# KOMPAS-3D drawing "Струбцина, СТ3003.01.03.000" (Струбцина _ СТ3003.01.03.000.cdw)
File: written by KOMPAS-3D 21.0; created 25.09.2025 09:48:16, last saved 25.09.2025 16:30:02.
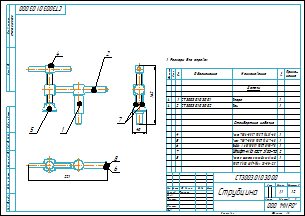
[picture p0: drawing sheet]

Sheet 1: A3, landscape

Document properties: Масса: 1.103282

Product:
- Part/product: Струбцина  | designation СТ3003.01.03.000
    Масса: 1.103282
    Форматы листов документа: A3
  - Component [detail]: Опора  | designation СТ3003.01.03.001  | pos. 1  | Материал: Круг$d30 ГОСТ 2590-2006;40Х ГОСТ 4543-2016$ (density 7850 kg/m3); Масса: 0.339602; Форматы листов документа: A4; source file: ..\..\3D\Струбцина _ СТ3003.01.03.000\Опора _ СТ3003.01.03.001.m3d, Опора _ СТ3003.01.03.001.cdw
  - Component [detail]: Ось  | designation СТ3003.01.03.002  | pos. 2  | Материал: Круг$d30 ГОСТ 2590-2006;40Х ГОСТ 4543-2016$ (density 7850 kg/m3); Масса: 0.346686; Форматы листов документа: A4; source file: ..\..\3D\Струбцина _ СТ3003.01.03.000\Ось _ СТ3003.01.03.002.m3d, Ось _ СТ3003.01.03.002.cdw
  - Component [standard]: Штифт 4x16 ГОСТ 3128-70  | qty 2  | pos. 7  | Материал: Сталь 45 ГОСТ 1050-88 (density 1000 kg/m3); Масса: 0.00158; Раздел спецификации: Стандартные изделия; Рассекать на разрезах: no
  - Component [standard]: Шайба A 6.01.10.019 ГОСТ 6958-78  | pos. 6  | Масса: 0.002792; Раздел спецификации: Стандартные изделия; Рассекать на разрезах: no
  - Component [standard]: Винт 7006-0537 ГОСТ 13431-68  | pos. 4  | Материал: Сталь 40Х ГОСТ 4543-2016 (density 1000 kg/m3); Масса: 0.294; Раздел спецификации: Стандартные изделия; Рассекать на разрезах: no; additional columns: 7006-0537
  - Component [standard]: Пята 7007-0035 ГОСТ 13437-68  | pos. 5  | Материал: Сталь 40Х ГОСТ 4543-2016 (density 1000 kg/m3); Масса: 0.116; Раздел спецификации: Стандартные изделия; Рассекать на разрезах: no; additional columns: 7007-0035
  - Component [standard]: Винт с шестигранной головкой ГОСТ Р ИСО 4017-М6 x 25-5.8-A2P  | pos. 8  | Материал: Сталь (density 1000 kg/m3); Масса: 0.001042; Раздел спецификации: Стандартные изделия; Рассекать на разрезах: no; additional columns: ГОСТ Р ИСО 4017-2013; М6 x 25 - 5.8 - A2P
- Part/product: Струбцина  | designation СТ3003.01.03.000-01
    Масса: 1.075052
  - Component [standard]: Болт М6-6gx25.58.019 ГОСТ 7798-70  | pos. 5  | Масса: 0.007871; Раздел спецификации: Стандартные изделия; Рассекать на разрезах: no
  - Component [standard]: Штифт 4x16 ГОСТ 3128-70  | qty 2  | pos. 7  | Материал: Сталь 45 ГОСТ 1050-88 (density 1000 kg/m3); Масса: 0.00158; Раздел спецификации: Стандартные изделия; Рассекать на разрезах: no
  - Component [standard]: Шайба A 6.01.10.019 ГОСТ 6958-78  | pos. 6  | Масса: 0.002792; Раздел спецификации: Стандартные изделия; Рассекать на разрезах: no
  - Component [standard]: Пята 7007-0035 ГОСТ 13437-68  | pos. 5  | Материал: Сталь 40Х ГОСТ 4543-2016 (density 1000 kg/m3); Масса: 0.116; Раздел спецификации: Стандартные изделия; Рассекать на разрезах: no; additional columns: 7007-0035
  - Component [standard]: Винт 7006-0537 ГОСТ 13431-68  | pos. 4  | Материал: Сталь 40Х ГОСТ 4543-2016 (density 1000 kg/m3); Масса: 0.294; Раздел спецификации: Стандартные изделия; Рассекать на разрезах: no; additional columns: 7006-0537
  - Component [detail]: Ось  | designation СТ3003.01.03.002  | pos. 2  | Материал: Круг$d30 ГОСТ 2590-2006;40Х ГОСТ 4543-2016$ (density 7850 kg/m3); Масса: 0.346686; Форматы листов документа: A4; source file: ..\..\3D\Струбцина _ СТ3003.01.03.000\Ось _ СТ3003.01.03.002.m3d, Ось _ СТ3003.01.03.002.cdw
  - Component [detail]: Опора  | designation СТ3003.01.03.001  | pos. 1  | Материал: Круг$d30 ГОСТ 2590-2006;40Х ГОСТ 4543-2016$ (density 7850 kg/m3); Масса: 0.339602; Форматы листов документа: A4; source file: ..\..\3D\Струбцина _ СТ3003.01.03.000\Опора _ СТ3003.01.03.001.m3d, Опора _ СТ3003.01.03.001.cdw
- Part/product: Струбцина  | designation СТ3003.01.03.000-02
    Масса: 1.075052
  - Component [detail]: Опора  | designation СТ3003.01.03.001  | pos. 1  | Материал: Круг$d30 ГОСТ 2590-2006;40Х ГОСТ 4543-2016$ (density 7850 kg/m3); Масса: 0.339602; Форматы листов документа: A4; source file: ..\..\3D\Струбцина _ СТ3003.01.03.000\Опора _ СТ3003.01.03.001.m3d, Опора _ СТ3003.01.03.001.cdw
  - Component [detail]: Ось  | designation СТ3003.01.03.002  | pos. 2  | Материал: Круг$d30 ГОСТ 2590-2006;40Х ГОСТ 4543-2016$ (density 7850 kg/m3); Масса: 0.346686; Форматы листов документа: A4; source file: ..\..\3D\Струбцина _ СТ3003.01.03.000\Ось _ СТ3003.01.03.002.m3d, Ось _ СТ3003.01.03.002.cdw
  - Component [standard]: Винт 7006-0537 ГОСТ 13431-68  | pos. 4  | Материал: Сталь 40Х ГОСТ 4543-2016 (density 1000 kg/m3); Масса: 0.294; Раздел спецификации: Стандартные изделия; Рассекать на разрезах: no; additional columns: 7006-0537
  - Component [standard]: Пята 7007-0035 ГОСТ 13437-68  | pos. 5  | Материал: Сталь 40Х ГОСТ 4543-2016 (density 1000 kg/m3); Масса: 0.116; Раздел спецификации: Стандартные изделия; Рассекать на разрезах: no; additional columns: 7007-0035
  - Component [standard]: Штифт 4x16 ГОСТ 3128-70  | qty 2  | pos. 7  | Материал: Сталь 45 ГОСТ 1050-88 (density 1000 kg/m3); Масса: 0.00158; Раздел спецификации: Стандартные изделия; Рассекать на разрезах: no
  - Component [standard]: Шайба A 6.01.10.019 ГОСТ 6958-78  | pos. 6  | Масса: 0.002792; Раздел спецификации: Стандартные изделия; Рассекать на разрезах: no
  - Component [standard]: Болт М6-6gx25.58.019 ГОСТ 7798-70  | pos. 5  | Масса: 0.007871; Раздел спецификации: Стандартные изделия; Рассекать на разрезах: no

Title block, sheet 1: Наименование: Струбцина; designation: СТ3003.01.03.000; Масса: 1,1; Количество листов документа: 1; organisation: ООО "МИРО"; Форматы листов документа: A3; stored path: C:\Users\1\Yandex.Disk\Документы\Новая папка\Стапель №2\Стапель _ СТ3003.00.00.000\Опора _ СТ3003.01.00.000\2D\Струбцина _ СТ3003.01.03.000\Струбцина _ СТ3003.01.03.000.cdw; Разработал: Тимонин

Views: Вид 1, Вид:1, Проекционный вид 3
Referenced files in C:\Users\1\Yandex.Disk\Документы\Новая папка\Стапель №2\Стапель _ СТ3003.00.00.000\Опора _ СТ3003.01.00.000\3D\Струбцина _ СТ3003.01.03.000\: Струбцина _ СТ3003.01.03.000.a3d, Опора _ СТ3003.01.03.001.m3d, Ось _ СТ3003.01.03.002.m3d
Referenced files in C:\Users\1\Yandex.Disk\Документы\Новая папка\Стапель №2\Стапель _ СТ3003.00.00.000\Опора _ СТ3003.01.00.000\2D\Струбцина _ СТ3003.01.03.000\: Опора _ СТ3003.01.03.001.cdw, Ось _ СТ3003.01.03.002.cdw
Referenced files in C:\Program Files\ASCON\KOMPAS-3D v21\Libs\PartLib\DATA\VAULT\Methods\Kompas\3D\Holding_devices\13447_13430_13431_13426_8921\: PLib_Pin_GOST_3128-70_813.m3d, Plib_Screw_GOST_13433_13435_813.m3d, Plib_Screw_GOST_13431-68_813.a3d
Referenced files in C:\Program Files\ASCON\KOMPAS-3D v21\Libs\PartLib\DATA\VAULT\Methods\Kompas\3D\: PLib_Piata_GOST_13437-68_813.m3d, PLib_Pin_3128_712.m3d, PLib_Washer_1_712.m3d, PLib_Bolt_1_ISO_1100.m3d
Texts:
  СТ3003.01.03.001
  Опора
  Винт 7006-0537 ГОСТ 13431-68
  Элемент станочного приспособления
  Винт
  ГОСТ
  СТ3003.01.03.002
  Ось
  Штифт 4x16 ГОСТ 3128-70
  Крепежное изделие ГОСТ
  Штифт
  Болт М6-6gx25.58.019 ГОСТ 7798-70
  Винт с шестигранной головкой
  ГОСТ Р ИСО
  Болт
  Шайба A 6.01.10.019 ГОСТ 6958-78
  Шайба
  Пята 7007-0035 ГОСТ 13437-68
  Пята
  ГОСТ Р ИСО 4017-М6 x 25-5.8-A2P
  СТ3003.01.00.000
  СТ3003.01.03.001 Опора
  СТ3003.01.03.002 Ось
  ГОСТ 3128-70 Штифты цилиндрические
  ГОСТ 13429-68 Винты нажимные с концом под пяту
  Рукоятка ГОСТ 13447-68
  Винт с шестигранной головкой ГОСТ Р ИСО 4017-М6 x 25-5.8-A2P
  СТ3003.01.03.000 Струбцина
Dimensions and other numbers on the sheet: 1; 2; 4; 5; 8; 6; 221; 7006-0537; 68; 58; 40Х; 019; 5.8; 01; 10; 7007-0035; 7; 1:2; 1,1

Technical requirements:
  Размеры для справок.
